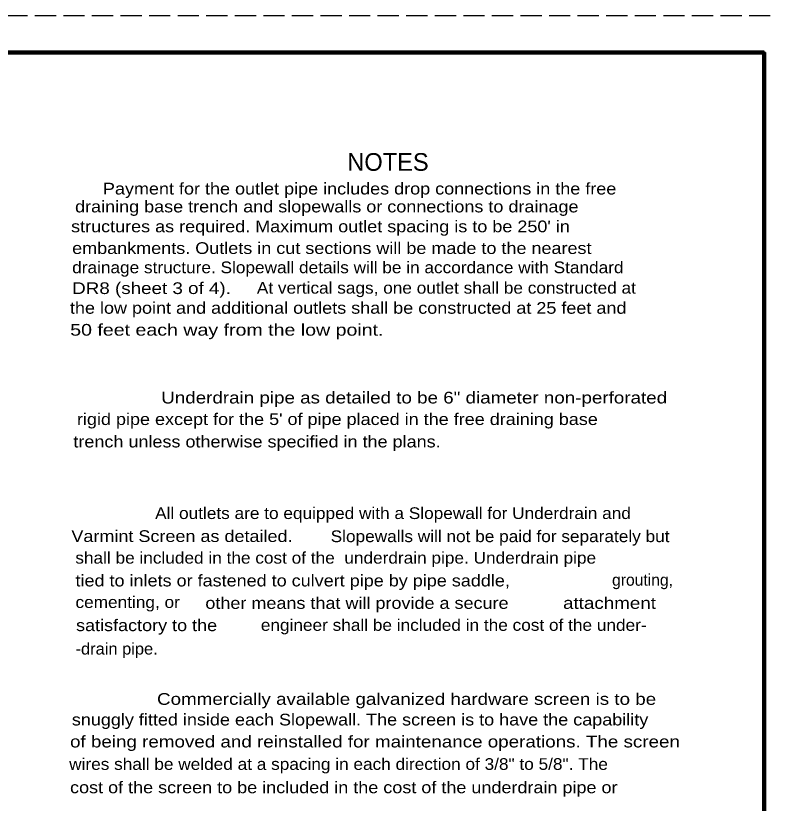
# Model space of a CAD drawing. Extents: x -48732 to -48696.6, y -117659.8 to -117637.8.
# Drawn here: x -48707.01 to -48696.76, y -117648.54 to -117637.85 of the extents above; entities that cross this region are included whole.
import ezdxf

# ---------------------------------------------------------------- set-up
doc = ezdxf.new("R2010")
doc.units = 0
doc.header["$LTSCALE"] = 0.048
doc.header["$PDMODE"] = 32
doc.header["$PDSIZE"] = 0.024
doc.linetypes.add('LONG_DASHED', pattern=[7.5, 6, -1.5])
doc.layers.add('1', color=7, linetype='Continuous', lineweight=25)
doc.layers.add('3', color=7, linetype='Continuous', lineweight=35)

msp = doc.modelspace()

# ---------------------------------------------------------------- linework, layer by layer
at = {"layer": '1', "linetype": 'LONG_DASHED'}
msp.add_line((-48696.76492, -117637.84817), (-48731.96492, -117637.84817), dxfattribs=at)
at = {"layer": '1', "lineweight": 158}
msp.add_line((-48696.84825, -117638.34817), (-48729.34825, -117638.34817), dxfattribs=at)
msp.add_lwpolyline([(-48696.84825, -117638.34817), (-48696.84825, -117659.34817), (-48729.34825, -117659.34817)], dxfattribs=at)
at = {"layer": '1'}
msp.add_point((-48696.84825, -117638.34817), dxfattribs=at)

# ---------------------------------------------------------------- texts
for s, width, p in [('Payment for the outlet pipe includes drop connections in the free ', 1.15, (-48705.82825, -117640.27592)), ('draining base trench and slopewalls or connections to drainage ', 1.15, (-48706.20683, -117640.51917)), ("structures as required. Maximum outlet spacing is to be 250' in", 1.15, (-48706.26075, -117640.78883)), ('embankments. Outlets in cut sections will be made to the nearest', 1.15, (-48706.24617, -117641.08358)), ('drainage structure. Slopewall details will be in accordance with Standard', 1.1, (-48706.24592, -117641.34525)), ('DR8 (sheet 3 of 4).', 1.2, (-48706.24592, -117641.62792)), (' At vertical sags, one outlet shall be constructed at ', 1.1, (-48703.80258, -117641.623)), ('the low point and additional outlets shall be constructed at 25 feet and', 1.15, (-48706.27625, -117641.89575)), ('50 feet each way from the low point.', 1.25, (-48706.27267, -117642.1935)), ('Underdrain pipe as detailed to be 6" diameter non-perforated', 1.2, (-48705.03617, -117643.11458)), ("rigid pipe except for the 5' of pipe placed in the free draining base ", 1.15, (-48706.18108, -117643.407)), ('trench unless otherwise specified in the plans.', 1.15, (-48706.22983, -117643.71167)), ('All outlets are to equipped with a Slopewall for Underdrain and', 1.1, (-48705.1195, -117644.68375)), ('Varmint Screen as detailed.', 1.15, (-48706.25692, -117644.99575)), ('Varmint Screen as detailed.', 1.15, (-48706.25692, -117644.99575)), ('Slopewalls will not be paid for separately but ', 1.1, (-48702.73533, -117644.99775)), ('shall be included in the cost of the  underdrain pipe. Underdrain pipe', 1.1, (-48706.20308, -117645.28975)), ('tied to inlets or fastened to culvert pipe by pipe saddle,', 1.15, (-48706.20067, -117645.59942)), ('cementing, or', 1.1, (-48706.20075, -117645.89217)), ('other means that will provide a secure', 1.15, (-48704.43733, -117645.90408)), ('attachment ', 1.2, (-48699.57933, -117645.904)), ('satisfactory to the ', 1.15, (-48706.19333, -117646.2065)), ('engineer shall be included in the cost of the under-', 1.1, (-48703.68383, -117646.20258)), ('-drain pipe.', 1.05, (-48706.20067, -117646.52458)), ('Commercially available galvanized hardware screen is to be ', 1.2, (-48705.09325, -117647.20767)), ('snuggly fitted inside each Slopewall. The screen is to have the capability ', 1.15, (-48706.25042, -117647.48792)), ('of being removed and reinstalled for maintenance operations. The screen ', 1.2, (-48706.27483, -117647.7865)), ('wires shall be welded at a spacing in each direction of 3/8" to 5/8". The ', 1.1, (-48706.287, -117648.09117)), ('cost of the screen to be included in the cost of the underdrain pipe or', 1.15, (-48706.27483, -117648.408))]:
    msp.add_text(s, height=0.159, dxfattribs=dict(at, width=width)).set_placement(p)
msp.add_text('grouting, ', height=0.159, dxfattribs=at).set_placement((-48698.9135, -117645.58967))
at = {"layer": '3'}
msp.add_text('NOTES', height=0.24, dxfattribs=at).set_placement((-48702.50967, -117639.95417))

doc.saveas('drawing.dxf')
